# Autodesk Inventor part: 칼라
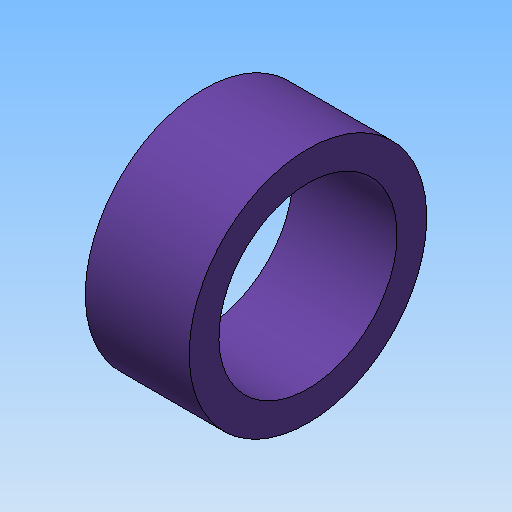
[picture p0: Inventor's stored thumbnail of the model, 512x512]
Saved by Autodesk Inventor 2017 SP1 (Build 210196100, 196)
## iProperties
Created: 2020-04
Part Number: 칼라
Material: 강철, 연강
Document SubType Name: Modeling
Designer: mduedu
Density: 7.86 g/cm^3
Mass: 4.83981 g
Surface Area: 7.91681 cm^2
Volume: 0.615752 cm^3
Appearance: 보라색
Author: mduedu
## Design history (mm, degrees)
sketch "스케치1"
  geometry: C1 r 8 at (0, 0); C2 r 6 at (0, 0); 1 further point
  constraints: 2 centre point, 2 coincident
  dimensions: "d0" = 16 diameter of C1; "d1" = 12 diameter of C2
extrude "돌출1" new body sketch "스케치1" distance "d2" = 7; taper "d3" = 0 deg
node "솔리드1"
